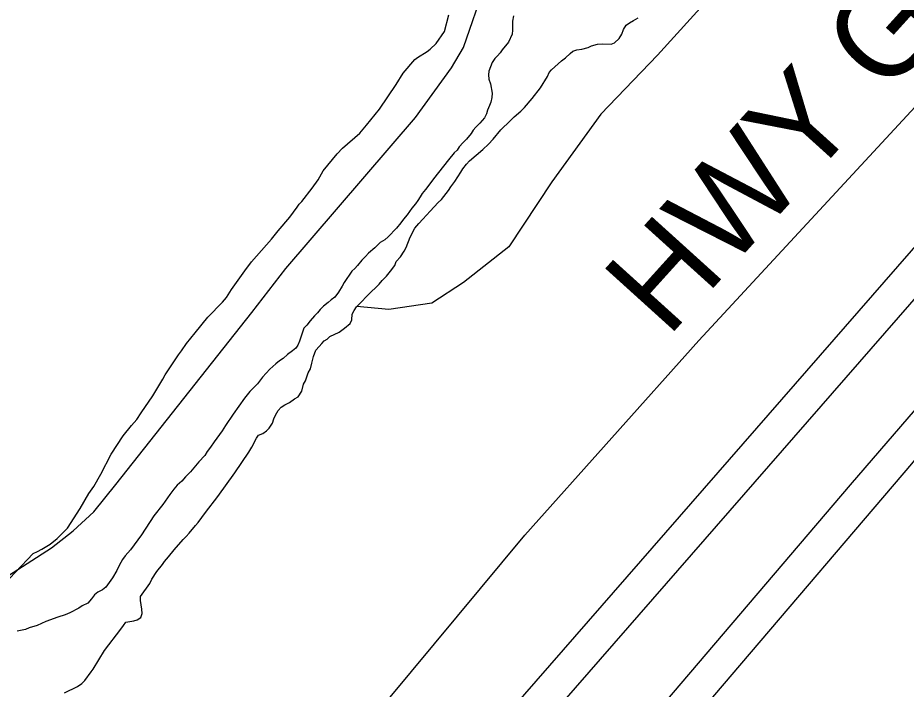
# Model space of a CAD drawing. Extents: x 3192927 to 3230760, y 831141 to 856475.
# Drawn here: x 3197342 to 3198132, y 843284 to 843881 of the extents above; entities that cross this region are included whole.
import ezdxf

# ---------------------------------------------------------------- set-up
doc = ezdxf.new("R2010")
doc.units = 0
for name, color, linetype in [('V-LEVE-TOET', 7, 'Continuous'), ('V-RIVR-GAGE-IDEN', 7, 'Continuous'), ('V-ROAD-CNTR', 7, 'Continuous'), ('V-SITE-VEGE', 7, 'Continuous'), ('V-SURV-LINE', 7, 'Continuous'), ('V-TOPO-SHOR', 7, 'Continuous')]:
    doc.layers.add(name, color=color, linetype=linetype)

msp = doc.modelspace()

# ---------------------------------------------------------------- linework, layer by layer
at = {"layer": 'V-LEVE-TOET'}
for points in [[(3197116.22, 842652.95), (3197268.54, 842817.59), (3197455.4, 843032.8), (3197652.42, 843251.99), (3197792.66, 843420.87), (3197947.63, 843593.94), (3198195.55, 843861.96), (3198411.79, 844109.62), (3198589.31, 844288), (3198599, 844299.14), (3198604.42, 844308.44), (3198601.98, 844315), (3198592.46, 844324.33)], [(3198708.32, 844176.12), (3198632.38, 844099.62), (3198339.6, 843764.1), (3198082.17, 843465.44), (3197856.09, 843200.47), (3197544.51, 842840.06), (3197251.84, 842508.77)]]:
    msp.add_lwpolyline(points, dxfattribs=at)
at = {"layer": 'V-ROAD-CNTR'}
msp.add_lwpolyline([(3197323.8, 843379.08), (3197371.65, 843409.46), (3197390.87, 843424.59), (3197409.15, 843441.7), (3197428.91, 843465.93), (3197549.92, 843619.02), (3197580.11, 843657.95), (3197695.47, 843792.32), (3197727.41, 843836.73), (3197738.24, 843854.67), (3197757.47, 843910.76), (3197764.58, 843949.92), (3197766.66, 843982.04), (3197762.91, 844015.28), (3197760.72, 844045.89), (3197759.43, 844059.89), (3197754.79, 844069.75), (3197747.77, 844075.12), (3197737.46, 844078.95), (3197728.15, 844083.72), (3197718.6, 844092.07), (3197568.67, 844249.73), (3197322.06, 844523.14)], dxfattribs=at)
at = {"layer": 'V-SITE-VEGE'}
for p, q in [((3197961.97, 843904.53), (3197910.67, 843847.75)), ((3197721.18, 843869.09), (3197725.1, 843883.63)), ((3197782.74, 843882.85), (3197781.65, 843878)), ((3197781.65, 843878), (3197781.79, 843870.2)), ((3197880.61, 843870.75), (3197882.98, 843874.59)), ((3197882.98, 843874.59), (3197885.95, 843876.79)), ((3197885.95, 843876.79), (3197889.57, 843878.66)), ((3197889.57, 843878.66), (3197893.53, 843881.16)), ((3197713.77, 843858.22), (3197721.18, 843869.09)), ((3197781.38, 843866.63), (3197778.29, 843859.56)), ((3197781.79, 843870.2), (3197781.38, 843866.63)), ((3197876.84, 843862.71), (3197879.21, 843866.56)), ((3197879.21, 843866.56), (3197880.61, 843870.75)), ((3197708.45, 843853.15), (3197713.77, 843858.22)), ((3197778.29, 843859.56), (3197772.59, 843852.55)), ((3197851.98, 843856.16), (3197857.54, 843857.65)), ((3197857.54, 843857.65), (3197861.45, 843857.88)), ((3197861.45, 843857.88), (3197869.57, 843857.69)), ((3197869.57, 843857.69), (3197872.52, 843858.92)), ((3197872.52, 843858.92), (3197876.84, 843862.71)), ((3197697.22, 843845.94), (3197705.8, 843851.26)), ((3197705.8, 843851.26), (3197708.45, 843853.15)), ((3197770.91, 843849.98), (3197768.57, 843847.44)), ((3197772.59, 843852.55), (3197770.91, 843849.98)), ((3197832.97, 843849.47), (3197835.61, 843851.35)), ((3197835.61, 843851.35), (3197838.89, 843852.58)), ((3197838.89, 843852.58), (3197843.46, 843853.11)), ((3197843.46, 843853.11), (3197849.02, 843854.61)), ((3197849.02, 843854.61), (3197851.98, 843856.16)), ((3197684.54, 843831.95), (3197694.9, 843844.05)), ((3197694.9, 843844.05), (3197697.22, 843845.94)), ((3197765.91, 843844.91), (3197763.55, 843841.39)), ((3197768.57, 843847.44), (3197765.91, 843844.91)), ((3197816.37, 843834.92), (3197825.33, 843842.83)), ((3197825.33, 843842.83), (3197828.98, 843845.66)), ((3197828.98, 843845.66), (3197832.97, 843849.47)), ((3197910.67, 843847.75), (3197860.47, 843795.34)), ((3197763.55, 843841.39), (3197760.76, 843833.66)), ((3197814.35, 843832.36), (3197816.37, 843834.92)), ((3197678.11, 843821.7), (3197684.54, 843831.95)), ((3197760.76, 843833.66), (3197760.36, 843830.42)), ((3197760.36, 843830.42), (3197760.59, 843826.51)), ((3197760.59, 843826.51), (3197762.11, 843822.24)), ((3197806.56, 843818.9), (3197812.97, 843828.82)), ((3197812.97, 843828.82), (3197814.35, 843832.36)), ((3197663.29, 843799.96), (3197678.11, 843821.7)), ((3197762.11, 843822.24), (3197763.54, 843814.09)), ((3197799.18, 843809.33), (3197806.56, 843818.9)), ((3197763.45, 843810.19), (3197762.37, 843805.99)), ((3197763.54, 843814.09), (3197763.45, 843810.19)), ((3197761.33, 843803.09), (3197759.6, 843798.91)), ((3197762.37, 843805.99), (3197761.33, 843803.09)), ((3197792.48, 843801.37), (3197799.18, 843809.33)), ((3197651.9, 843785.61), (3197663.29, 843799.96)), ((3197758.55, 843795.69), (3197756.84, 843792.15)), ((3197759.6, 843798.91), (3197758.55, 843795.69)), ((3197783.19, 843793.14), (3197789.16, 843798.19)), ((3197789.16, 843798.19), (3197792.48, 843801.37)), ((3197860.47, 843795.34), (3197816.82, 843735.28)), ((3197752.82, 843787.37), (3197749.17, 843783.88)), ((3197756.84, 843792.15), (3197752.82, 843787.37)), ((3197771.53, 843781.39), (3197779.84, 843789.32)), ((3197779.84, 843789.32), (3197783.19, 843793.14)), ((3197630.6, 843764.99), (3197645.88, 843778.6)), ((3197645.88, 843778.6), (3197651.9, 843785.61)), ((3197746.82, 843781.01), (3197745.12, 843778.13)), ((3197749.17, 843783.88), (3197746.82, 843781.01)), ((3197764.5, 843773.11), (3197771.53, 843781.39)), ((3197740.78, 843773.03), (3197737.78, 843770.18)), ((3197745.12, 843778.13), (3197740.78, 843773.03)), ((3197760.5, 843768.66), (3197764.5, 843773.11)), ((3197625.61, 843760.24), (3197630.6, 843764.99)), ((3197732.42, 843763.48), (3197729.76, 843760.95)), ((3197734.44, 843766.36), (3197732.42, 843763.48)), ((3197737.78, 843770.18), (3197734.44, 843766.36)), ((3197743.57, 843753.79), (3197755.51, 843763.9)), ((3197755.51, 843763.9), (3197760.5, 843768.66)), ((3197613.21, 843744.94), (3197625.61, 843760.24)), ((3197724.74, 843754.9), (3197711.33, 843737.99)), ((3197729.76, 843760.95), (3197724.74, 843754.9)), ((3197737.55, 843746.79), (3197740.9, 843750.93)), ((3197740.9, 843750.93), (3197743.57, 843753.79)), ((3197608.8, 843736.92), (3197613.21, 843744.94)), ((3197730.45, 843735.58), (3197735.85, 843743.9)), ((3197735.85, 843743.9), (3197737.55, 843746.79)), ((3197603.42, 843729.57), (3197608.8, 843736.92)), ((3197708.98, 843734.47), (3197704.28, 843728.41)), ((3197711.33, 843737.99), (3197708.98, 843734.47)), ((3197726.76, 843730.8), (3197730.45, 843735.58)), ((3197816.82, 843735.28), (3197778.62, 843677.42)), ((3197594.36, 843717.76), (3197603.42, 843729.57)), ((3197701.27, 843724.91), (3197699.57, 843721.7)), ((3197704.28, 843728.41), (3197701.27, 843724.91)), ((3197718.69, 843719.61), (3197724.73, 843727.59)), ((3197724.73, 843727.59), (3197726.76, 843730.8)), ((3197592.03, 843715.22), (3197594.36, 843717.76)), ((3197695.52, 843715.62), (3197692.18, 843711.8)), ((3197697.54, 843718.5), (3197695.52, 843715.62)), ((3197699.57, 843721.7), (3197697.54, 843718.5)), ((3197708.37, 843709.14), (3197715.7, 843716.76)), ((3197715.7, 843716.76), (3197718.69, 843719.61)), ((3197583.62, 843703.72), (3197590.02, 843712.67)), ((3197590.02, 843712.67), (3197592.03, 843715.22)), ((3197692.18, 843711.8), (3197688.13, 843705.72)), ((3197702.01, 843701.82), (3197708.37, 843709.14)), ((3197573.26, 843691.62), (3197583.62, 843703.72)), ((3197684.79, 843701.91), (3197682.44, 843698.71)), ((3197688.13, 843705.72), (3197684.79, 843701.91)), ((3197698.35, 843698), (3197702.01, 843701.82)), ((3197567.23, 843684.29), (3197573.26, 843691.62)), ((3197678.42, 843693.93), (3197671.09, 843686.31)), ((3197682.44, 843698.71), (3197678.42, 843693.93)), ((3197690.58, 843685.84), (3197695, 843693.86)), ((3197695, 843693.86), (3197698.35, 843698)), ((3197549.52, 843663.92), (3197567.23, 843684.29)), ((3197671.09, 843686.31), (3197668.1, 843683.45)), ((3197687.11, 843676.82), (3197690.58, 843685.84)), ((3197659.16, 843676.52), (3197653.52, 843671.78)), ((3197664.14, 843681.28), (3197659.16, 843676.52)), ((3197668.1, 843683.45), (3197664.14, 843681.28)), ((3197685.41, 843673.61), (3197687.11, 843676.82)), ((3197778.62, 843677.42), (3197738.24, 843645.75)), ((3197650.84, 843668.6), (3197647.84, 843665.42)), ((3197653.52, 843671.78), (3197650.84, 843668.6)), ((3197678.36, 843664.36), (3197682.04, 843668.49)), ((3197682.04, 843668.49), (3197685.41, 843673.61)), ((3197543.47, 843655.94), (3197549.52, 843663.92)), ((3197643.82, 843660.64), (3197641.48, 843658.1)), ((3197647.84, 843665.42), (3197643.82, 843660.64)), ((3197673.28, 843655.7), (3197676.98, 843660.82)), ((3197676.98, 843660.82), (3197678.36, 843664.36)), ((3197531.7, 843639.32), (3197543.47, 843655.94)), ((3197638.83, 843655.56), (3197632.09, 843645.64)), ((3197641.48, 843658.1), (3197638.83, 843655.56)), ((3197669.6, 843651.24), (3197673.28, 843655.7)), ((3197632.09, 843645.64), (3197630.06, 843642.44)), ((3197652.94, 843634.42), (3197663.25, 843644.24)), ((3197663.25, 843644.24), (3197665.93, 843647.43)), ((3197665.93, 843647.43), (3197669.6, 843651.24)), ((3197738.24, 843645.75), (3197709.86, 843627.19)), ((3197527.31, 843632.28), (3197531.7, 843639.32)), ((3197627, 843636.99), (3197623.65, 843632.52)), ((3197630.06, 843642.44), (3197627, 843636.99)), ((3197523.63, 843628.14), (3197527.31, 843632.28)), ((3197620.34, 843630.33), (3197617.68, 843627.79)), ((3197623.65, 843632.52), (3197620.34, 843630.33)), ((3197646.27, 843627.1), (3197652.94, 843634.42)), ((3197510.63, 843614.8), (3197523.63, 843628.14)), ((3197610.71, 843621.46), (3197608.36, 843618.59)), ((3197613.71, 843624.64), (3197610.71, 843621.46)), ((3197617.68, 843627.79), (3197613.71, 843624.64)), ((3197643.35, 843624.33), (3197646.27, 843627.1)), ((3197671.67, 843621.73), (3197643.35, 843624.33)), ((3197709.86, 843627.19), (3197671.67, 843621.73)), ((3197499.25, 843600.77), (3197510.63, 843614.8)), ((3197605.7, 843616.06), (3197601.69, 843611.6)), ((3197608.36, 843618.59), (3197605.7, 843616.06)), ((3197596, 843604.91), (3197594.95, 843601.36)), ((3197598.68, 843607.77), (3197596, 843604.91)), ((3197601.69, 843611.6), (3197598.68, 843607.77)), ((3197491.54, 843591.21), (3197499.25, 843600.77)), ((3197594.95, 843601.36), (3197592.15, 843593.31)), ((3197487.16, 843584.81), (3197491.54, 843591.21)), ((3197590.77, 843589.76), (3197589.08, 843587.2)), ((3197592.15, 843593.31), (3197590.77, 843589.76)), ((3197472.67, 843563.39), (3197484.48, 843581.3)), ((3197484.48, 843581.3), (3197487.16, 843584.81)), ((3197581.47, 843581.54), (3197577.81, 843578.05)), ((3197586.09, 843584.68), (3197581.47, 843581.54)), ((3197589.08, 843587.2), (3197586.09, 843584.68)), ((3197571.2, 843573.33), (3197565.88, 843568.59)), ((3197574.51, 843575.85), (3197571.2, 843573.33)), ((3197577.81, 843578.05), (3197574.51, 843575.85)), ((3197565.88, 843568.59), (3197559.21, 843561.27)), ((3197461.82, 843544.8), (3197470.63, 843559.54)), ((3197470.63, 843559.54), (3197472.67, 843563.39)), ((3197559.21, 843561.27), (3197554.84, 843555.53)), ((3197554.84, 843555.53), (3197548.17, 843548.54)), ((3197451.39, 843529.77), (3197461.82, 843544.8)), ((3197543.16, 843542.81), (3197533.06, 843528.43)), ((3197548.17, 843548.54), (3197543.16, 843542.81)), ((3197447.34, 843523.7), (3197451.39, 843529.77)), ((3197533.06, 843528.43), (3197526.33, 843518.51)), ((3197435.29, 843509.04), (3197442.66, 843518.28)), ((3197442.66, 843518.28), (3197447.34, 843523.7)), ((3197526.33, 843518.51), (3197523.29, 843513.71)), ((3197523.29, 843513.71), (3197516.22, 843503.81)), ((3197424.5, 843492.72), (3197435.29, 843509.04)), ((3197516.22, 843503.81), (3197513.18, 843499)), ((3197510.17, 843495.17), (3197508.13, 843491.65)), ((3197513.18, 843499), (3197510.17, 843495.17)), ((3197415.3, 843475.07), (3197424.5, 843492.72)), ((3197508.13, 843491.65), (3197502.79, 843485.93)), ((3197502.79, 843485.93), (3197495.1, 843477.01)), ((3197409.18, 843464.16), (3197415.3, 843475.07)), ((3197490.77, 843472.57), (3197487.43, 843468.75)), ((3197495.1, 843477.01), (3197490.77, 843472.57)), ((3197404.81, 843457.77), (3197409.18, 843464.16)), ((3197483.45, 843465.27), (3197480.44, 843461.76)), ((3197487.43, 843468.75), (3197483.45, 843465.27)), ((3197397.01, 843444.63), (3197404.81, 843457.77)), ((3197476.75, 843456.98), (3197470.68, 843448.02)), ((3197480.44, 843461.76), (3197476.75, 843456.98)), ((3197470.68, 843448.02), (3197462.64, 843438.14)), ((3197385.87, 843427.02), (3197397.01, 843444.63)), ((3197462.64, 843438.14), (3197451.51, 843421.19)), ((3197376.54, 843417.82), (3197385.87, 843427.02)), ((3197370.25, 843412.77), (3197376.54, 843417.82)), ((3197451.51, 843421.19), (3197441.76, 843407.77)), ((3197359.04, 843406.22), (3197362.99, 843408.4)), ((3197362.99, 843408.4), (3197370.25, 843412.77)), ((3197441.76, 843407.77), (3197437.08, 843402.36)), ((3197323.43, 843371.36), (3197355.1, 843404.36)), ((3197355.1, 843404.36), (3197359.04, 843406.22)), ((3197434.73, 843399.16), (3197431.67, 843393.71)), ((3197437.08, 843402.36), (3197434.73, 843399.16)), ((3197431.67, 843393.71), (3197429.62, 843389.21)), ((3197429.62, 843389.21), (3197425.89, 843382.8)), ((3197425.89, 843382.8), (3197419.84, 843374.49)), ((3197409.92, 843367.58), (3197407.23, 843364.07)), ((3197412.91, 843370.11), (3197409.92, 843367.58)), ((3197416.86, 843372.29), (3197412.91, 843370.11)), ((3197419.84, 843374.49), (3197416.86, 843372.29)), ((3197403.89, 843360.25), (3197398.96, 843357.77)), ((3197407.23, 843364.07), (3197403.89, 843360.25)), ((3197395.99, 843355.89), (3197387.76, 843351.54)), ((3197398.96, 843357.77), (3197395.99, 843355.89)), ((3197366.45, 843343.93), (3197358.89, 843340.54)), ((3197377.27, 843347.89), (3197366.45, 843343.93)), ((3197383.82, 843350.01), (3197377.27, 843347.89)), ((3197387.76, 843351.54), (3197383.82, 843350.01)), ((3197348.4, 843336.89), (3197340.9, 843335.44)), ((3197351.69, 843338.43), (3197348.4, 843336.89)), ((3197358.89, 843340.54), (3197351.69, 843338.43))]:
    msp.add_line(p, q, dxfattribs=at)
at = {"layer": 'V-SURV-LINE'}
for points in [[(3197205.37, 842606.26), (3198699.59, 844319.04)], [(3198722.19, 844299.31), (3197227.96, 842586.53)]]:
    msp.add_lwpolyline(points, dxfattribs=at)
at = {"layer": 'V-TOPO-SHOR'}
for points in [[(3197782.74, 843882.85), (3197781.65, 843878), (3197781.79, 843870.2), (3197781.38, 843866.63), (3197778.29, 843859.56), (3197772.59, 843852.55), (3197770.91, 843849.98), (3197768.57, 843847.44), (3197765.91, 843844.91), (3197763.55, 843841.39), (3197760.76, 843833.66), (3197760.36, 843830.42), (3197760.59, 843826.51), (3197762.11, 843822.24), (3197763.54, 843814.09), (3197763.45, 843810.19), (3197762.37, 843805.99), (3197761.33, 843803.09), (3197759.6, 843798.91), (3197758.55, 843795.68), (3197756.84, 843792.15), (3197752.82, 843787.37), (3197749.17, 843783.88), (3197746.82, 843781.01), (3197745.12, 843778.13), (3197740.78, 843773.03), (3197737.78, 843770.18), (3197734.44, 843766.36), (3197732.42, 843763.48), (3197729.76, 843760.95), (3197724.74, 843754.9), (3197711.33, 843737.99), (3197708.98, 843734.47), (3197704.28, 843728.41), (3197701.27, 843724.91), (3197699.57, 843721.7), (3197697.54, 843718.5), (3197695.52, 843715.62), (3197692.18, 843711.8), (3197688.13, 843705.72), (3197684.79, 843701.91), (3197682.44, 843698.71), (3197678.42, 843693.93), (3197671.09, 843686.31), (3197668.1, 843683.45), (3197664.14, 843681.28), (3197659.16, 843676.52), (3197653.52, 843671.78), (3197650.84, 843668.6), (3197647.84, 843665.42), (3197643.82, 843660.64), (3197641.48, 843658.1), (3197638.83, 843655.56), (3197632.09, 843645.64), (3197630.06, 843642.44), (3197627, 843636.99), (3197623.65, 843632.52), (3197620.34, 843630.33), (3197617.68, 843627.79), (3197613.71, 843624.64), (3197610.71, 843621.46), (3197608.36, 843618.59), (3197605.7, 843616.06), (3197601.69, 843611.6), (3197598.68, 843607.77), (3197596, 843604.91), (3197594.95, 843601.36), (3197592.15, 843593.31), (3197590.77, 843589.76), (3197589.08, 843587.2), (3197586.09, 843584.68), (3197581.47, 843581.54), (3197577.81, 843578.05), (3197574.51, 843575.85), (3197571.2, 843573.33), (3197565.88, 843568.59), (3197559.21, 843561.27)], [(3197698.35, 843698), (3197702.01, 843701.82), (3197708.37, 843709.14), (3197715.7, 843716.76), (3197718.69, 843719.61), (3197724.73, 843727.59), (3197726.76, 843730.8), (3197730.45, 843735.58), (3197735.85, 843743.9), (3197737.55, 843746.79), (3197740.9, 843750.93), (3197743.57, 843753.79), (3197755.51, 843763.9), (3197760.5, 843768.66), (3197764.5, 843773.11), (3197771.53, 843781.39), (3197779.84, 843789.32), (3197783.19, 843793.14), (3197789.16, 843798.19), (3197792.48, 843801.37), (3197799.18, 843809.33), (3197806.56, 843818.9), (3197812.97, 843828.82), (3197814.36, 843832.36), (3197816.37, 843834.92), (3197825.33, 843842.83), (3197828.98, 843845.66), (3197832.97, 843849.47), (3197835.61, 843851.35), (3197838.89, 843852.58), (3197843.46, 843853.11), (3197849.02, 843854.61), (3197851.98, 843856.16), (3197857.54, 843857.65), (3197861.45, 843857.88), (3197869.57, 843857.69), (3197872.52, 843858.92), (3197876.84, 843862.71), (3197879.21, 843866.56), (3197880.61, 843870.75), (3197882.97, 843874.59), (3197885.95, 843876.79), (3197889.57, 843878.66), (3197893.53, 843881.16)], [(3197609.59, 843588.66), (3197612.25, 843591.2), (3197614.26, 843593.75), (3197616.9, 843595.31), (3197619.23, 843597.53), (3197627.45, 843601.56), (3197632.41, 843605.01), (3197637.38, 843609.12), (3197638.76, 843612.33), (3197639.21, 843617.53), (3197640.91, 843620.73), (3197642.94, 843623.93), (3197646.27, 843627.1), (3197652.94, 843634.42), (3197663.25, 843644.24), (3197665.93, 843647.43), (3197669.6, 843651.24), (3197673.28, 843655.71), (3197676.98, 843660.82), (3197678.36, 843664.36), (3197682.04, 843668.49), (3197685.41, 843673.61), (3197687.11, 843676.82), (3197690.58, 843685.84), (3197695, 843693.86), (3197698.35, 843698)], [(3198247.67, 843601.69), (3198205.6, 843567.51), (3198136.72, 843484.36), (3197817.02, 843109.29), (3197700.47, 842948.31), (3197582.13, 842808.54), (3197585.68, 842790.87), (3197592.76, 842783.8), (3197608.68, 842774.98), (3197624.6, 842766.15), (3197640.53, 842746.71), (3197652.91, 842730.81), (3197660, 842718.44), (3197668.85, 842704.31), (3197679.47, 842691.94), (3197683, 842688.41)], [(3197383.12, 843280.48), (3197394.63, 843286.05), (3197398.6, 843288.88), (3197401.26, 843291.42), (3197406.97, 843299.08), (3197408.66, 843301.64), (3197418.81, 843318.29), (3197433.24, 843337.12), (3197435.59, 843340.32), (3197437.62, 843343.52), (3197444.79, 843344.65), (3197447.74, 843345.55), (3197451.04, 843347.42), (3197452.1, 843350.97), (3197451.87, 843354.88), (3197450.75, 843362.7), (3197450.84, 843366.27), (3197458.92, 843377.78), (3197460.96, 843381.63), (3197465.35, 843388.35), (3197470.38, 843394.73), (3197472.06, 843397.29), (3197475.73, 843401.43), (3197480.76, 843407.81), (3197488.78, 843417.04), (3197491.45, 843419.57), (3197494.12, 843422.44), (3197499.81, 843429.45), (3197502.15, 843431.99), (3197508.54, 843440.94), (3197519.61, 843455.3), (3197534.74, 843476.38), (3197547.2, 843494.61), (3197549.91, 843499.09), (3197554, 843507.12), (3197555.69, 843509.68), (3197559.63, 843511.21), (3197562.94, 843513.73), (3197565.27, 843515.95), (3197568.3, 843520.43), (3197569.37, 843524.3), (3197570.74, 843527.52), (3197573.12, 843531.69), (3197575.79, 843534.55), (3197579.09, 843536.74), (3197583.37, 843538.92), (3197587.67, 843542.06), (3197590.96, 843543.93), (3197594.34, 843549.05), (3197595.78, 843555.19), (3197597.48, 843558.08), (3197599.93, 843565.17), (3197601.96, 843568.7), (3197603.06, 843573.87), (3197604.82, 843579.68), (3197606.91, 843585.48), (3197609.59, 843588.66)], [(3197559.21, 843561.27), (3197554.84, 843555.53), (3197548.17, 843548.54), (3197543.16, 843542.81), (3197533.06, 843528.43), (3197526.33, 843518.51), (3197523.29, 843513.71), (3197516.22, 843503.81), (3197513.18, 843499), (3197510.17, 843495.17), (3197508.13, 843491.65), (3197502.79, 843485.93), (3197495.1, 843477.01), (3197490.77, 843472.57), (3197487.43, 843468.75), (3197483.45, 843465.27), (3197480.44, 843461.76), (3197476.75, 843456.98), (3197470.68, 843448.02), (3197462.64, 843438.14), (3197451.51, 843421.19), (3197441.76, 843407.77), (3197437.08, 843402.36), (3197434.73, 843399.16), (3197431.67, 843393.71), (3197429.62, 843389.21), (3197425.89, 843382.8), (3197419.84, 843374.49), (3197416.86, 843372.29), (3197412.91, 843370.11), (3197409.92, 843367.58), (3197407.23, 843364.07), (3197403.89, 843360.25), (3197398.96, 843357.77), (3197395.99, 843355.89), (3197387.76, 843351.54), (3197383.82, 843350.01), (3197377.27, 843347.89), (3197366.45, 843343.93), (3197358.89, 843340.54), (3197351.69, 843338.43), (3197348.4, 843336.89), (3197340.89, 843335.44)]]:
    msp.add_lwpolyline(points, dxfattribs=at)

# ---------------------------------------------------------------- texts
at = {"layer": 'V-RIVR-GAGE-IDEN'}
msp.add_text('HWY GAGE', height=83, rotation=47.86995, dxfattribs=at).set_placement((3197919.76, 843595.67))

doc.saveas('drawing.dxf')
